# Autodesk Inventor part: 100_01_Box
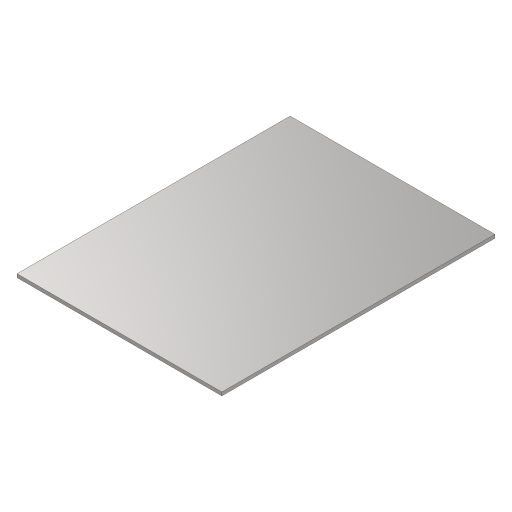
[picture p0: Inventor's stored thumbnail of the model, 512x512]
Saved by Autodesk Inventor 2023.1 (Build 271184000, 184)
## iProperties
Category: Autodesk® Inventor® Tutorial Series
Company: Fabian Stasiak CAD Consulting
Created: 2022-05
Part Number: 100_01_Box
Material: Steel
Document SubType Name: Sheet Metal
Designer: F.Stasiak
Density: 7.85 g/cm^3
Sheet Metal Rule: Steel 2.5 mm/Round
Appearance: Stainless - Brushed
Catalog Web Link: www.expertbooks.eu
Thickness: 2,5
FLATAREA: =<FLAT PATTERN AREA>
Author: F.Stasiak
Subject: Sheet Metal Design. Basic and Advanced techniques
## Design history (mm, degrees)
node "Face1"
  sketch "Sketch1"
    geometry: L1 (75, 100)-(-75, 100); L2 (-75, 100)-(-75, -100); L3 (-75, -100)-(75, -100); L4 (75, -100)-(75, 100); L5 (75, 100)-(-75, -100); L6 (-75, 100)-(75, -100); 1 further point
    constraints: 12 end point, 2 midpoint, 2 parallel, 1 horizontal, 1 perpendicular
    dimensions: "d0" = 150 distance of L3.end L2.end; "d1" = 200 distance of L2.end L1.end
body "Solid1"
face "Plate1" dims "d2" = 2.5 (= Thickness)
other parameters: "Thickness" = 2.5 (derived), "BendRadius" = 2.5 (= Thickness), "BendReliefWidth" = 2.5 (= Thickness), "BendReliefDepth" = 1.25 (= 0.5 x Thickness), "SeamGap" = 0.01, "MinimumRemnant" = 5 (= 2 x Thickness), "TransitionRadius" = 2.5 (= BendRadius), "JacobiRadiusSize" = 2.5 (= BendRadius), "GapSize" = 2.5 (= Thickness)
